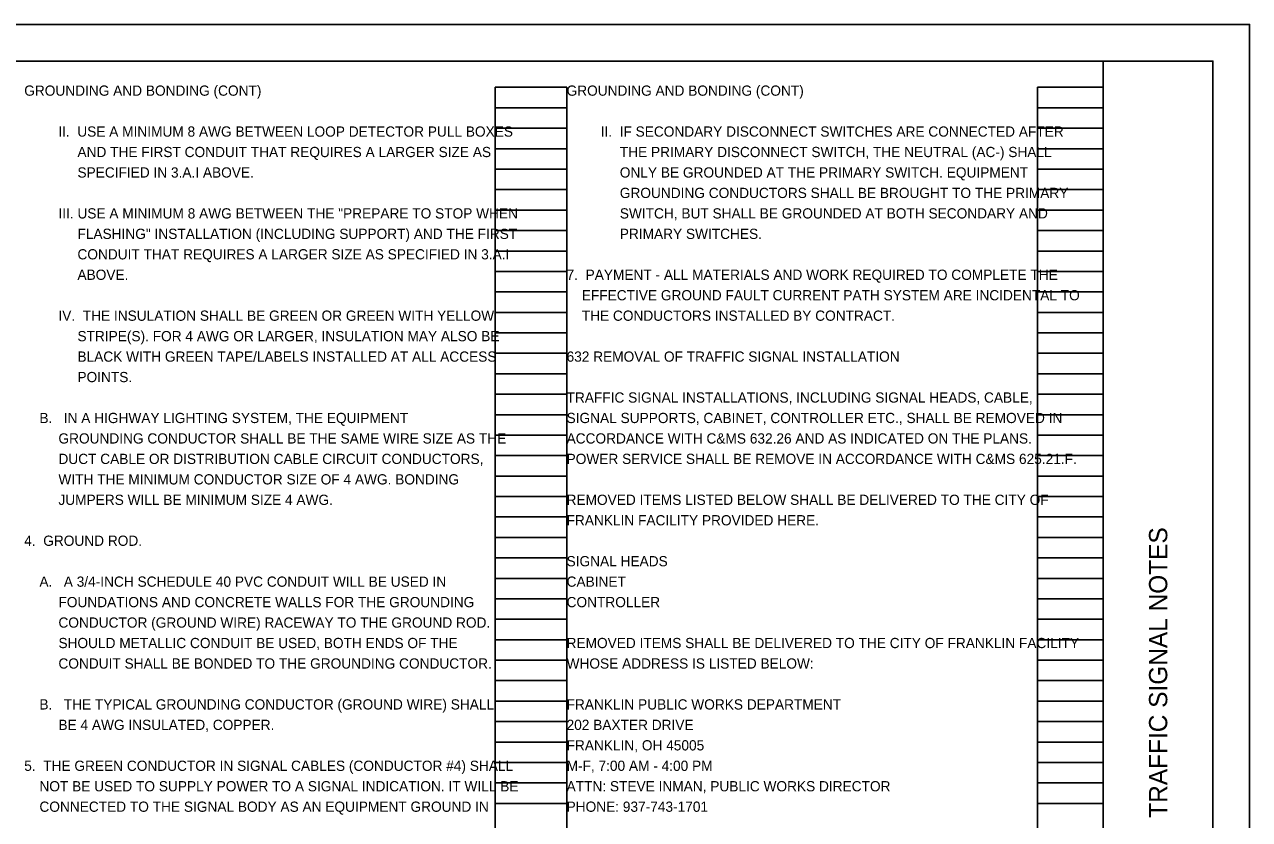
# Model space of a CAD drawing. Extents: x 0 to 34, y 0 to 22.
# Drawn here: x 17.24 to 34, y 11.12 to 22 of the extents above; entities that cross this region are included whole.
import ezdxf

# ---------------------------------------------------------------- set-up
doc = ezdxf.new("R2010")
doc.units = 0
for name, color, linetype in [('SH_Border', 7, 'Continuous'), ('SH_Cut_Line', 7, 'Continuous'), ('SH_Data', 7, 'Continuous'), ('SH_Text', 7, 'Continuous')]:
    doc.layers.add(name, color=color, linetype=linetype)

msp = doc.modelspace()

# ---------------------------------------------------------------- linework, layer by layer
at = {"layer": 'SH_Border'}
msp.add_line((32, 0.5), (32, 21.5), dxfattribs=at)
msp.add_lwpolyline([(1.5, 21.5), (33.5, 21.5), (33.5, 0.5), (1.5, 0.5)], close=True, dxfattribs=at)
at = {"layer": 'SH_Cut_Line'}
msp.add_lwpolyline([(0, 0), (34, 0), (34, 22), (0, 22)], close=True, dxfattribs=at)
at = {"layer": 'SH_Data'}
for p, q in [((23.68, 0.98), (23.68, 21.14)), ((23.68, 21.14), (24.66, 21.14)), ((24.66, 0.98), (24.66, 21.14)), ((31.1, 0.98), (31.1, 21.14)), ((31.1, 21.14), (32, 21.14)), ((32, 0.98), (32, 21.14)), ((23.68, 20.86), (24.66, 20.86)), ((31.1, 20.86), (32, 20.86)), ((23.68, 20.58), (24.66, 20.58)), ((31.1, 20.58), (32, 20.58)), ((23.68, 20.3), (24.66, 20.3)), ((31.1, 20.3), (32, 20.3)), ((23.68, 20.02), (24.66, 20.02)), ((31.1, 20.02), (32, 20.02)), ((23.68, 19.74), (24.66, 19.74)), ((31.1, 19.74), (32, 19.74)), ((23.68, 19.46), (24.66, 19.46)), ((31.1, 19.46), (32, 19.46)), ((23.68, 19.18), (24.66, 19.18)), ((31.1, 19.18), (32, 19.18)), ((23.68, 18.9), (24.66, 18.9)), ((31.1, 18.9), (32, 18.9)), ((23.68, 18.62), (24.66, 18.62)), ((31.1, 18.62), (32, 18.62)), ((23.68, 18.34), (24.66, 18.34)), ((31.1, 18.34), (32, 18.34)), ((23.68, 18.06), (24.66, 18.06)), ((31.1, 18.06), (32, 18.06)), ((23.68, 17.78), (24.66, 17.78)), ((31.1, 17.78), (32, 17.78)), ((23.68, 17.5), (24.66, 17.5)), ((31.1, 17.5), (32, 17.5)), ((23.68, 17.22), (24.66, 17.22)), ((31.1, 17.22), (32, 17.22)), ((23.68, 16.94), (24.66, 16.94)), ((31.1, 16.94), (32, 16.94)), ((23.68, 16.66), (24.66, 16.66)), ((31.1, 16.66), (32, 16.66)), ((23.68, 16.38), (24.66, 16.38)), ((31.1, 16.38), (32, 16.38)), ((23.68, 16.1), (24.66, 16.1)), ((31.1, 16.1), (32, 16.1)), ((23.68, 15.82), (24.66, 15.82)), ((31.1, 15.82), (32, 15.82)), ((23.68, 15.54), (24.66, 15.54)), ((31.1, 15.54), (32, 15.54)), ((23.68, 15.26), (24.66, 15.26)), ((31.1, 15.26), (32, 15.26)), ((23.68, 14.98), (24.66, 14.98)), ((31.1, 14.98), (32, 14.98)), ((23.68, 14.7), (24.66, 14.7)), ((31.1, 14.7), (32, 14.7)), ((23.68, 14.42), (24.66, 14.42)), ((31.1, 14.42), (32, 14.42)), ((23.68, 14.14), (24.66, 14.14)), ((31.1, 14.14), (32, 14.14)), ((23.68, 13.86), (24.66, 13.86)), ((31.1, 13.86), (32, 13.86)), ((23.68, 13.58), (24.66, 13.58)), ((31.1, 13.58), (32, 13.58)), ((23.68, 13.3), (24.66, 13.3)), ((31.1, 13.3), (32, 13.3)), ((23.68, 13.02), (24.66, 13.02)), ((31.1, 13.02), (32, 13.02)), ((23.68, 12.74), (24.66, 12.74)), ((31.1, 12.74), (32, 12.74)), ((23.68, 12.46), (24.66, 12.46)), ((31.1, 12.46), (32, 12.46)), ((23.68, 12.18), (24.66, 12.18)), ((31.1, 12.18), (32, 12.18)), ((23.68, 11.9), (24.66, 11.9)), ((31.1, 11.9), (32, 11.9)), ((23.68, 11.62), (24.66, 11.62)), ((31.1, 11.62), (32, 11.62)), ((23.68, 11.34), (24.66, 11.34)), ((31.1, 11.34), (32, 11.34))]:
    msp.add_line(p, q, dxfattribs=at)

# ---------------------------------------------------------------- texts
msp.add_text('TRAFFIC SIGNAL NOTES', height=0.25, rotation=90, dxfattribs=at).set_placement((32.875, 11.144))
at = {"layer": 'SH_Text'}
for s, p in [('GROUNDING AND BONDING (CONT)', (17.237, 21.025)), ('GROUNDING AND BONDING (CONT)', (24.657, 21.025)), ('        II.  USE A MINIMUM 8 AWG BETWEEN LOOP DETECTOR PULL BOXES', (17.287, 20.465)), ('        II.  IF SECONDARY DISCONNECT SWITCHES ARE CONNECTED AFTER', (24.707, 20.465)), ('              AND THE FIRST CONDUIT THAT REQUIRES A LARGER SIZE AS', (17.237, 20.185)), ('              THE PRIMARY DISCONNECT SWITCH, THE NEUTRAL (AC-) SHALL', (24.657, 20.185)), ('              SPECIFIED IN 3.A.I ABOVE.', (17.237, 19.905)), ('              ONLY BE GROUNDED AT THE PRIMARY SWITCH. EQUIPMENT', (24.657, 19.905)), ('              GROUNDING CONDUCTORS SHALL BE BROUGHT TO THE PRIMARY ', (24.657, 19.625)), ('         III. USE A MINIMUM 8 AWG BETWEEN THE "PREPARE TO STOP WHEN', (17.237, 19.345)), ('              SWITCH, BUT SHALL BE GROUNDED AT BOTH SECONDARY AND', (24.657, 19.345)), ('              FLASHING" INSTALLATION (INCLUDING SUPPORT) AND THE FIRST', (17.237, 19.065)), ('              PRIMARY SWITCHES.', (24.657, 19.065)), ('              CONDUIT THAT REQUIRES A LARGER SIZE AS SPECIFIED IN 3.A.I', (17.237, 18.785)), ('              ABOVE.', (17.237, 18.505)), ('7.  PAYMENT - ALL MATERIALS AND WORK REQUIRED TO COMPLETE THE', (24.657, 18.505)), ('    EFFECTIVE GROUND FAULT CURRENT PATH SYSTEM ARE INCIDENTAL TO', (24.657, 18.225)), ('         IV.  THE INSULATION SHALL BE GREEN OR GREEN WITH YELLOW', (17.237, 17.945)), ('    THE CONDUCTORS INSTALLED BY CONTRACT.', (24.657, 17.945)), ('              STRIPE(S). FOR 4 AWG OR LARGER, INSULATION MAY ALSO BE', (17.237, 17.665)), ('              BLACK WITH GREEN TAPE/LABELS INSTALLED AT ALL ACCESS', (17.237, 17.385)), ('632 REMOVAL OF TRAFFIC SIGNAL INSTALLATION', (24.657, 17.385)), ('              POINTS.', (17.237, 17.105)), ('TRAFFIC SIGNAL INSTALLATIONS, INCLUDING SIGNAL HEADS, CABLE, ', (24.657, 16.825)), ('    B.   IN A HIGHWAY LIGHTING SYSTEM, THE EQUIPMENT', (17.237, 16.545)), ('SIGNAL SUPPORTS, CABINET, CONTROLLER ETC., SHALL BE REMOVED IN ', (24.657, 16.545)), ('         GROUNDING CONDUCTOR SHALL BE THE SAME WIRE SIZE AS THE', (17.237, 16.265)), ('ACCORDANCE WITH C&MS 632.26 AND AS INDICATED ON THE PLANS. ', (24.657, 16.265)), ('         DUCT CABLE OR DISTRIBUTION CABLE CIRCUIT CONDUCTORS, ', (17.237, 15.985)), ('POWER SERVICE SHALL BE REMOVE IN ACCORDANCE WITH C&MS 625.21.F.', (24.657, 15.985)), ('         WITH THE MINIMUM CONDUCTOR SIZE OF 4 AWG. BONDING', (17.237, 15.705)), ('         JUMPERS WILL BE MINIMUM SIZE 4 AWG.', (17.237, 15.425)), ('REMOVED ITEMS LISTED BELOW SHALL BE DELIVERED TO THE CITY OF ', (24.657, 15.425)), ('FRANKLIN FACILITY PROVIDED HERE.', (24.657, 15.145)), ('4.  GROUND ROD.', (17.237, 14.865)), ('SIGNAL HEADS', (24.657, 14.585)), ('    A.   A 3/4-INCH SCHEDULE 40 PVC CONDUIT WILL BE USED IN', (17.237, 14.305)), ('CABINET', (24.657, 14.305)), ('         FOUNDATIONS AND CONCRETE WALLS FOR THE GROUNDING', (17.237, 14.025)), ('CONTROLLER', (24.657, 14.025)), ('         CONDUCTOR (GROUND WIRE) RACEWAY TO THE GROUND ROD.', (17.237, 13.745)), ('         SHOULD METALLIC CONDUIT BE USED, BOTH ENDS OF THE ', (17.237, 13.465)), ('REMOVED ITEMS SHALL BE DELIVERED TO THE CITY OF FRANKLIN FACILITY ', (24.657, 13.465)), ('         CONDUIT SHALL BE BONDED TO THE GROUNDING CONDUCTOR.', (17.237, 13.185)), ('WHOSE ADDRESS IS LISTED BELOW:', (24.657, 13.185)), ('    B.   THE TYPICAL GROUNDING CONDUCTOR (GROUND WIRE) SHALL', (17.237, 12.625)), ('FRANKLIN PUBLIC WORKS DEPARTMENT', (24.657, 12.625)), ('         BE 4 AWG INSULATED, COPPER.', (17.237, 12.345)), ('202 BAXTER DRIVE', (24.657, 12.345)), ('FRANKLIN, OH 45005', (24.657, 12.065)), ('5.  THE GREEN CONDUCTOR IN SIGNAL CABLES (CONDUCTOR #4) SHALL', (17.237, 11.785)), ('M-F, 7:00 AM - 4:00 PM', (24.657, 11.785)), ('    NOT BE USED TO SUPPLY POWER TO A SIGNAL INDICATION. IT WILL BE', (17.237, 11.505)), ('ATTN: STEVE INMAN, PUBLIC WORKS DIRECTOR', (24.657, 11.505)), ('    CONNECTED TO THE SIGNAL BODY AS AN EQUIPMENT GROUND IN ', (17.237, 11.225)), ('PHONE: 937-743-1701', (24.657, 11.225))]:
    msp.add_text(s, height=0.14, dxfattribs=at).set_placement(p)

doc.saveas('drawing.dxf')
